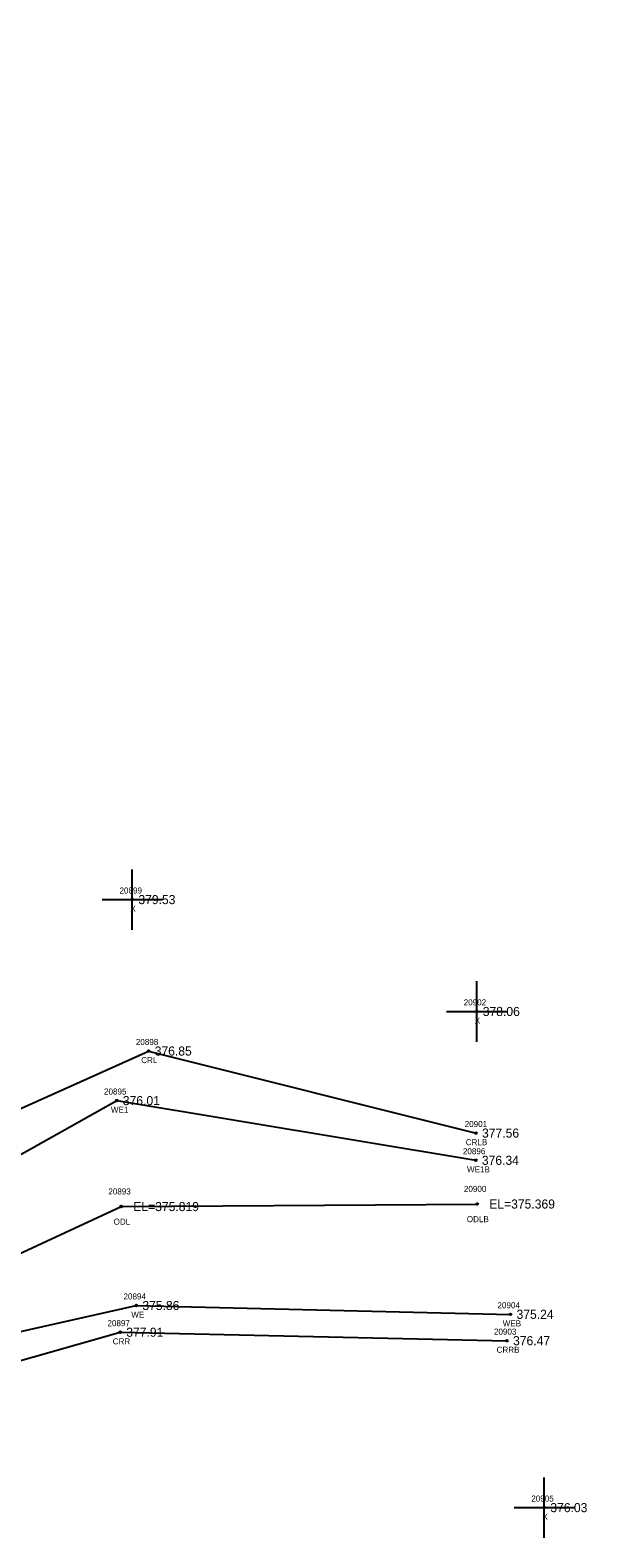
# Model space of a CAD drawing. Extents: x 2116373 to 2118139, y 979529 to 981026.
# Drawn here: x 2117731.3 to 2117823.4, y 979951.9 to 980201.2 of the extents above; entities that cross this region are included whole.
import ezdxf

# ---------------------------------------------------------------- set-up
doc = ezdxf.new("R2010")
doc.units = 0
for name, color, linetype in [('RD_EX_H2O', 7, 'Continuous'), ('RD_EX_H2O_txCode', 7, 'Continuous'), ('RD_EX_Misc', 7, 'Continuous'), ('RD_EX_Misc_txCode', 7, 'Continuous'), ('RD_EX_TX_H2O_ELEV', 7, 'Continuous'), ('RD_EX_TX_Misc_ELEV', 7, 'Continuous'), ('RD_SMD_Locator', 7, 'Continuous')]:
    doc.layers.add(name, color=color, linetype=linetype)

msp = doc.modelspace()

# ---------------------------------------------------------------- linework, layer by layer
at = {"layer": 'RD_EX_H2O'}
for points in [[(2117055.27, 980533.4), (2117084.87, 980468.5), (2117113.12, 980396.82), (2117150.26, 980360.48), (2117172.14, 980330.53), (2117167.4, 980300.56), (2117152, 980282.05), (2117153.33, 980268.31), (2117164.01, 980260.72), (2117221.6, 980247.26), (2117265.25, 980211.02), (2117324.27, 980199.15), (2117347.37, 980175.31), (2117365.85, 980182.55), (2117389.45, 980162.29), (2117399.63, 980142.01), (2117411.26, 980120.88), (2117420.42, 980068.64), (2117446.24, 980057.21), (2117497.11, 980045.39), (2117594.71, 979999.33), (2117646.33, 979985.56), (2117750.91, 980032.44), (2117805.09, 980018.87)], [(2117320.83, 980195.76), (2117348.44, 980166.4), (2117344.42, 980159.47), (2117364.05, 980141.59), (2117409.75, 980120.17), (2117416.75, 980067.62), (2117432.5, 980045.49), (2117502.17, 980039.14), (2117583.98, 979987.26), (2117646.81, 979981.12), (2117705, 980001.51), (2117745.64, 980024.24), (2117805.06, 980014.37)], [(2117327.56, 980176.76), (2117343.89, 980156.23), (2117361.71, 980140.22), (2117404.48, 980117.53), (2117412.59, 980065.44), (2117429.85, 980042.55), (2117500.31, 980032.76), (2117583.13, 979982.49), (2117644.33, 979974.23), (2117711.62, 979990.62), (2117746.36, 980006.72), (2117805.28, 980007.14)], [(2117334.27, 980149.08), (2117359.88, 980134.92), (2117396.25, 980116.57), (2117405.43, 980061.84), (2117428.2, 980035.31), (2117491.98, 980017.16), (2117553.53, 979985.3), (2117578.12, 979975.29), (2117646.29, 979963.95), (2117711.26, 979981.91), (2117748.87, 979990.36), (2117810.8, 979988.9)], [(2117558.11, 979977.26), (2117576.22, 979971.1), (2117644.97, 979961.23), (2117709.89, 979975.62), (2117746.21, 979985.94), (2117810.22, 979984.54)]]:
    msp.add_lwpolyline(points, dxfattribs=at)
at = {"layer": 'RD_EX_Misc'}
for p, q in [((2117748.21, 980052.48), (2117748.21, 980062.48)), ((2117743.21, 980057.48), (2117753.21, 980057.48)), ((2117805.21, 980033.98), (2117805.21, 980043.98)), ((2117800.21, 980038.98), (2117810.21, 980038.98)), ((2117816.39, 979951.94), (2117816.39, 979961.94)), ((2117811.39, 979956.94), (2117821.39, 979956.94))]:
    msp.add_line(p, q, dxfattribs=at)
at = {"layer": 'RD_SMD_Locator'}
for centre in [(2117748.21, 980057.48), (2117805.21, 980038.98), (2117750.91, 980032.44), (2117745.64, 980024.24), (2117805.09, 980018.87), (2117805.06, 980014.37), (2117746.36, 980006.72), (2117805.28, 980007.14), (2117748.87, 979990.36), (2117810.8, 979988.9), (2117746.21, 979985.94), (2117810.22, 979984.54), (2117816.39, 979956.94)]:
    msp.add_circle(centre, 0.15, dxfattribs=at)

# ---------------------------------------------------------------- texts
at = {"layer": 'RD_EX_H2O_txCode'}
for s, p in [('20898', (2117748.79, 980033.44)), ('CRL', (2117749.68, 980030.44)), ('20895', (2117743.52, 980025.24)), ('WE1', (2117744.66, 980022.24)), ('20901', (2117803.21, 980019.87)), ('CRLB', (2117803.39, 980016.87)), ('20896', (2117802.92, 980015.37)), ('WE1B', (2117803.6, 980012.37)), ('20900', (2117803.09, 980009.14)), ('20893', (2117744.24, 980008.72)), ('ODLB', (2117803.57, 980004.14)), ('ODL', (2117745.11, 980003.72)), ('20894', (2117746.75, 979991.36)), ('20904', (2117808.64, 979989.9)), ('20897', (2117744.09, 979986.94)), ('WE', (2117748.03, 979988.36)), ('WEB', (2117809.51, 979986.9)), ('CRR', (2117744.96, 979983.94)), ('20903', (2117808.06, 979985.54)), ('CRRB', (2117808.5, 979982.54))]:
    msp.add_text(s, height=1, dxfattribs=at).set_placement(p)
at = {"layer": 'RD_EX_Misc_txCode'}
for s, p in [('20899', (2117746.09, 980058.48)), ('X', (2117747.89, 980055.48)), ('20902', (2117803.05, 980039.98)), ('X', (2117804.89, 980036.98)), ('20905', (2117814.24, 979957.94)), ('X', (2117816.08, 979954.94))]:
    msp.add_text(s, height=1, dxfattribs=at).set_placement(p)
at = {"layer": 'RD_EX_TX_H2O_ELEV'}
for s, p in [('376.85', (2117751.91, 980031.69)), ('376.01', (2117746.64, 980023.49)), ('377.56', (2117806.09, 980018.12)), ('376.34', (2117806.06, 980013.62)), ('EL=375.819', (2117748.36, 980005.97)), ('EL=375.369', (2117807.28, 980006.39)), ('375.86', (2117749.87, 979989.61)), ('375.24', (2117811.8, 979988.15)), ('377.91', (2117747.21, 979985.19)), ('376.47', (2117811.22, 979983.79))]:
    msp.add_text(s, height=1.5, dxfattribs=at).set_placement(p)
at = {"layer": 'RD_EX_TX_Misc_ELEV'}
for s, p in [('379.53', (2117749.21, 980056.73)), ('378.06', (2117806.21, 980038.23)), ('376.03', (2117817.39, 979956.19))]:
    msp.add_text(s, height=1.5, dxfattribs=at).set_placement(p)

doc.saveas('drawing.dxf')
